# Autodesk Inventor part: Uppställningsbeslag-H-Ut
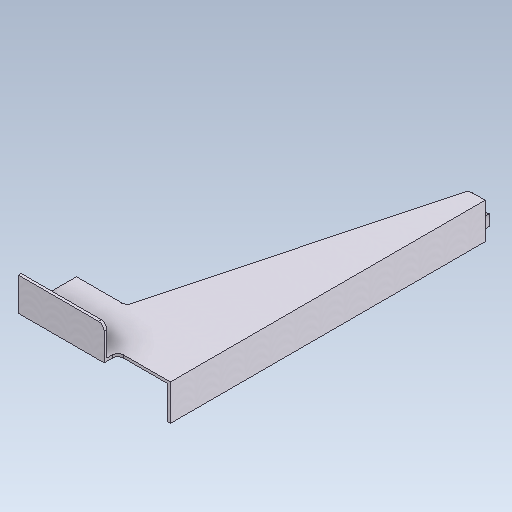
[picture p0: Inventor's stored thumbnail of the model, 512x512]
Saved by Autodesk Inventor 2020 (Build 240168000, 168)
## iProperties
Created: 2019-06
Part Number: Uppställningsbeslag-H-Ut
Material: Aluminum 6061, Welded
Document SubType Name: Modeling
Designer: cl
Density: 2.7 g/cm^3
Appearance: Weld - Aluminum
Author: cl
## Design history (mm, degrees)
sketch "Sketch1"
  geometry: L1 (95, 25)-(250, 25); L2 (250, 25)-(250, -80); L3 (250, -80)-(167.693, -80); L4 (0, 0)-(0, -570); L5 (0, -570)-(22.307, -570); L6 (31.973, -562.564)-(158.027, -87.436); L7 (95, 25)-(95, 10); L8 (85, 0)-(0, 0); A1 r 10 centre (167.693, -90) between (167.693, -80) and (158.027, -87.436); A2 r 10 centre (22.307, -560) between (22.307, -570) and (31.973, -562.564); A3 r 10 centre (85, 10) between (85, 0) and (95, 10); 4 further points
  constraints: 16 end point, 6 point on circle, 6 point on line, 6 tangent, 4 perpendicular, 3 centre point, 2 vertical, 1 coincident, 1 equal radius, 1 horizontal
  dimensions: "d1" = 105 distance of L1.end L2.end; "d3" = 90 distance of L2.end point (160, -80); "d4" = 570 distance of point (0, 0) L4.end; "d5" = 30 distance of L4.end point (30, -570); "d6" = 10 radius of A1; "d7" = 25 distance of L1.start point (95, 0); "d8" = 95 distance of L4.start point (95, 0); "d9" = 250 distance between parallel lines of L2 L4; "d10" = 10 radius of A3
extrude "Extrusion1" new body sketch "Sketch1" distance "d11" = 5; taper "d12" = 0 deg
sketch "Sketch2"
  geometry: L1 (-250, -25)-(-95, -25); L2 (-95, -25)-(-95, -20); L3 (-95, -20)-(-250, -20); L4 (-250, -20)-(-250, -25); L5 (-250, -25)-(-95, -25) reference; L6 (-250, 80)-(-250, -25) reference; L7 (-95, -25)-(-95, -10) reference; 1 further point
  constraints: 8 end point, 3 collinear, 2 parallel, 1 horizontal, 1 perpendicular
  dimensions: "d13" = 5 distance of L3.end L1.start
extrude "Extrusion2" join sketch "Sketch2" distance "d14" = 55; taper "d15" = 0 deg
fillet "Fillet1" dims "d16" = 10
sketch "Sketch3"
  geometry: L1 (0, 0)-(-5, 0); L2 (-5, 0)-(-5, -570); L3 (-5, -570)-(0, -570); L4 (0, -570)-(0, 0); L5 (0, 0)-(0, -570) reference; L6 (0, -570)-(-22.307, -570) reference; L7 (-85, 0)-(0, 0) reference
  constraints: 8 end point, 3 collinear, 2 parallel, 1 horizontal, 1 perpendicular
  dimensions: "d17" = 5 distance of L1.start L1.end
extrude "Extrusion3" join sketch "Sketch3" distance "d18" = 60; taper "d19" = 0 deg
sketch "Sketch4"
  geometry: L1 (5, -5)-(5, -65) reference; L2 (5, -30)-(25, -30); L3 (25, -30)-(25, -55); L4 (25, -55)-(5, -55); L5 (5, -55)-(5, -30); L6 (5, -5)-(22.307, -5) reference; 1 further point
  constraints: 8 end point, 2 parallel, 1 horizontal, 1 perpendicular, 1 point on line
  dimensions: "d20" = 25 distance of L2.end L3.end; "d21" = 20 distance of L2.start L2.end; "d22" = 25 distance between parallel lines of L6 L2
extrude "Extrusion4" join sketch "Sketch4" distance "d23" = 80; taper "d24" = 0 deg
sketch "Sketch5"
  geometry: L1 (22.5, -32.5)-(7.5, -32.5); L2 (7.5, -32.5)-(7.5, -52.5); L3 (7.5, -52.5)-(22.5, -52.5); L4 (22.5, -52.5)-(22.5, -32.5); L5 (25, -30)-(5, -30) reference; L6 (25, -55)-(25, -30) reference; 1 further point
  constraints: 8 end point, 2 parallel, 1 horizontal, 1 perpendicular
  dimensions: "d25" = 15 distance of L1.start L1.end; "d26" = 20 distance of L3.end L1.start; "d27" = 2.5 distance between parallel lines of L5 L1; "d28" = 2.5 distance between parallel lines of L4 L6
extrude "Extrusion5" join sketch "Sketch5" distance "d29" = 15; taper "d30" = 0 deg
fillet "Fillet2" dims "d31" = 15
body "Solid1"
